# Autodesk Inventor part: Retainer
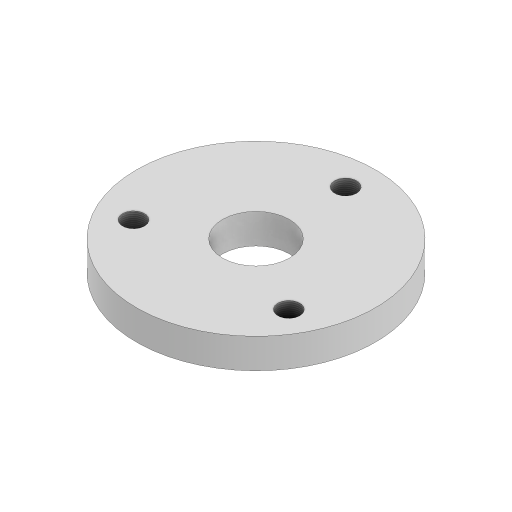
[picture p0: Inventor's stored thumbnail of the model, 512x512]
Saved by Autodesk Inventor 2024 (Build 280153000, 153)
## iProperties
Created: 2019-03
Part Number: Retainer
Material: Generic
Document SubType Name: Modeling
Designer: LENOVO-CADCIM
Density: 1 g/cm^3
Appearance: Default
Author: LENOVO-CADCIM
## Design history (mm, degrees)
sketch "Sketch1" dims "d1" = 150
  geometry: C1 r 100 at (0, 0); 3 further points
  constraints: 2 coincident, 1 centre point, 1 vertical alignment, 2 other
  dimensions: "d0" = 200 diameter of C1
extrude "Extrusion1" new body sketch "Sketch1" stored distance "d2" = 25; taper "d3" = 0 deg
sketch "Sketch2" dims "d4" = 150
  geometry: 3 further points
  constraints: 1 coincident, 1 vertical alignment, 2 other
hole "Hole1" sketch "Sketch2" at (0, 75) diameter "d5" = 18.376; stored, may be unused: countersink angle "d9" = 90 deg, drill point angle "d11" = 118 deg; dims "d6" = 40, "d7" = 4.4, "d8" = 2, "d10" = 47.3
pattern_circular "Circular Pattern1" dims angle "d13" = 360 deg
sketch "Sketch3"
  geometry: C1 r 28 at (0, 0); 1 further point
  constraints: 1 centre point, 1 coincident
  dimensions: "d15" = 56 diameter of C1
extrude "Extrusion2" cut sketch "Sketch3" distance "d16" = 25; taper "d17" = 0 deg
body "Solid1"
